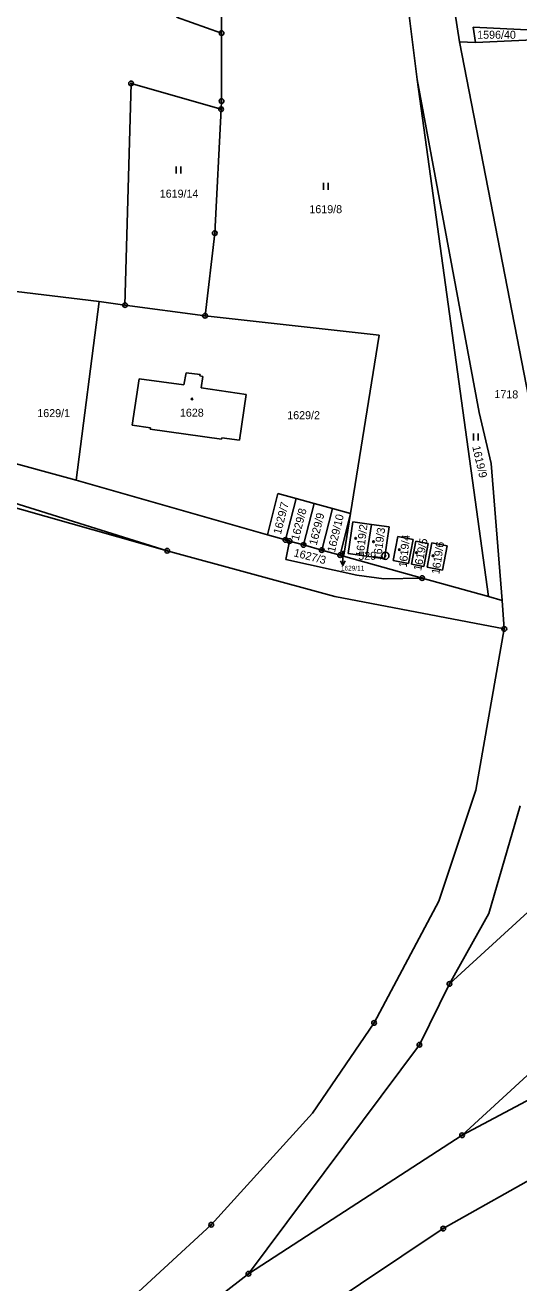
# Model space of a CAD drawing. Extents: x -763296 to -761805, y -1153670 to -1152034.
# Drawn here: x -762587.9 to -762483, y -1153075 to -1152808 of the extents above; entities that cross this region are included whole.
import ezdxf

# ---------------------------------------------------------------- set-up
doc = ezdxf.new("R2010")
doc.units = 0
for name, color, linetype in [('Vrstva 1', 7, 'Continuous'), ('Vrstva 16', 7, 'Continuous'), ('Vrstva 17', 7, 'Continuous'), ('Vrstva 18', 7, 'Continuous'), ('Vrstva 19', 7, 'Continuous'), ('Vrstva 24', 7, 'Continuous'), ('Vrstva 25', 7, 'Continuous'), ('Vrstva 62', 7, 'Continuous')]:
    doc.layers.add(name, color=color, linetype=linetype)

msp = doc.modelspace()

# ---------------------------------------------------------------- linework, layer by layer
at = {"layer": 'Vrstva 1'}
for p, q in [((-762508.36, -1152789.42), (-762504.64, -1152819.5)), ((-762499.2, -1152789.04), (-762495.62, -1152811.48)), ((-762546.17, -1152801.38), (-762546.17, -1152809.66)), ((-762546.17, -1152809.66), (-762555.78, -1152806.25)), ((-762546.17, -1152824.1), (-762546.17, -1152809.66)), ((-762492.69, -1152808.38), (-762492.22, -1152811.65)), ((-762469.39, -1152809.59), (-762492.69, -1152808.38)), ((-762469.13, -1152810.58), (-762492.22, -1152811.65)), ((-762492.22, -1152811.65), (-762495.62, -1152811.48)), ((-762495.62, -1152811.48), (-762480.87, -1152887.2)), ((-762566.69, -1152867.4), (-762565.41, -1152820.33)), ((-762565.41, -1152820.33), (-762546.26, -1152825.83)), ((-762504.64, -1152819.5), (-762491.44, -1152890.19)), ((-762504.64, -1152819.5), (-762489.47, -1152929.3)), ((-762546.26, -1152825.83), (-762546.17, -1152824.1)), ((-762546.26, -1152825.83), (-762547.62, -1152852.12)), ((-762547.62, -1152852.12), (-762549.69, -1152869.67)), ((-762572.19, -1152866.66), (-762622.59, -1152860.62)), ((-762572.19, -1152866.66), (-762577.03, -1152904.55)), ((-762566.69, -1152867.4), (-762572.19, -1152866.66)), ((-762549.69, -1152869.67), (-762566.69, -1152867.4)), ((-762549.69, -1152869.67), (-762512.7, -1152873.81)), ((-762518.78, -1152911.67), (-762512.7, -1152873.81)), ((-762554.17, -1152884.35), (-762553.71, -1152881.78)), ((-762553.71, -1152881.78), (-762550.74, -1152882.15)), ((-762550.74, -1152882.15), (-762550.77, -1152882.42)), ((-762550.77, -1152882.42), (-762550.12, -1152882.58)), ((-762550.12, -1152882.58), (-762550.5, -1152885)), ((-762565.16, -1152892.92), (-762563.68, -1152883.04)), ((-762563.68, -1152883.04), (-762554.17, -1152884.35)), ((-762550.5, -1152885), (-762540.93, -1152886.37)), ((-762540.93, -1152886.37), (-762542.33, -1152896.12)), ((-762491.44, -1152890.19), (-762488.88, -1152901.06)), ((-762561.28, -1152893.46), (-762565.16, -1152892.92)), ((-762561.33, -1152893.76), (-762561.28, -1152893.46)), ((-762546.16, -1152895.89), (-762561.33, -1152893.76)), ((-762546.12, -1152895.59), (-762546.16, -1152895.89)), ((-762542.33, -1152896.12), (-762546.12, -1152895.59)), ((-762577.03, -1152904.55), (-762602.71, -1152897.57)), ((-762616.34, -1152901.22), (-762557.73, -1152919.56)), ((-762488.88, -1152901.06), (-762486.58, -1152930.11)), ((-762612.33, -1152904.1), (-762557.73, -1152919.56)), ((-762536.44, -1152916.16), (-762577.03, -1152904.55)), ((-762536.44, -1152916.16), (-762534.2, -1152907.38)), ((-762534.2, -1152907.38), (-762530.35, -1152908.45)), ((-762530.35, -1152908.45), (-762532.6, -1152917.27)), ((-762530.35, -1152908.45), (-762526.49, -1152909.52)), ((-762526.49, -1152909.52), (-762528.74, -1152918.34)), ((-762526.49, -1152909.52), (-762522.64, -1152910.6)), ((-762522.64, -1152910.6), (-762524.89, -1152919.42)), ((-762522.64, -1152910.6), (-762518.78, -1152911.67)), ((-762518.78, -1152911.67), (-762520.98, -1152920.5)), ((-762520.13, -1152920.06), (-762518.78, -1152911.67)), ((-762518.26, -1152913.43), (-762519.27, -1152920.16)), ((-762518.26, -1152913.43), (-762514.34, -1152913.96)), ((-762514.34, -1152913.96), (-762515.35, -1152920.75)), ((-762514.34, -1152913.96), (-762510.56, -1152914.52)), ((-762510.56, -1152914.52), (-762511.58, -1152921.31)), ((-762532.6, -1152917.27), (-762536.44, -1152916.16)), ((-762531.74, -1152917.51), (-762532.6, -1152917.27)), ((-762532.54, -1152921.39), (-762531.74, -1152917.51)), ((-762531.74, -1152917.51), (-762528.74, -1152918.34)), ((-762509.71, -1152921.67), (-762508.73, -1152916.52)), ((-762508.73, -1152916.52), (-762505.49, -1152917.15)), ((-762505.49, -1152917.15), (-762506.47, -1152922.29)), ((-762505.83, -1152922.41), (-762504.9, -1152917.52)), ((-762504.9, -1152917.52), (-762502.25, -1152918.04)), ((-762557.73, -1152919.56), (-762522.11, -1152929.29)), ((-762528.74, -1152918.34), (-762524.89, -1152919.42)), ((-762524.89, -1152919.42), (-762520.98, -1152920.5)), ((-762520.13, -1152920.06), (-762520.24, -1152920.71)), ((-762519.27, -1152920.16), (-762515.35, -1152920.75)), ((-762502.25, -1152918.04), (-762503.18, -1152922.92)), ((-762502.47, -1152923.06), (-762501.48, -1152917.91)), ((-762501.48, -1152917.91), (-762498.24, -1152918.53)), ((-762498.24, -1152918.53), (-762499.23, -1152923.68)), ((-762517.46, -1152924.74), (-762532.54, -1152921.39)), ((-762520.98, -1152920.5), (-762520.24, -1152920.71)), ((-762520.24, -1152920.71), (-762503.56, -1152925.36)), ((-762515.35, -1152920.75), (-762511.58, -1152921.31)), ((-762506.47, -1152922.29), (-762509.71, -1152921.67)), ((-762503.18, -1152922.92), (-762505.83, -1152922.41)), ((-762511.67, -1152925.56), (-762517.46, -1152924.74)), ((-762503.56, -1152925.36), (-762511.67, -1152925.56)), ((-762503.56, -1152925.36), (-762489.47, -1152929.3)), ((-762499.23, -1152923.68), (-762502.47, -1152923.06)), ((-762486.1, -1152936.16), (-762522.11, -1152929.29)), ((-762489.47, -1152929.3), (-762486.58, -1152930.11)), ((-762486.58, -1152930.11), (-762486.1, -1152936.16)), ((-762486.1, -1152936.16), (-762492.13, -1152970.38)), ((-762492.13, -1152970.38), (-762500.03, -1152993.98)), ((-762482.73, -1152973.76), (-762489.42, -1152996.62)), ((-762461.33, -1152978.19), (-762497.75, -1153011.54)), ((-762500.03, -1152993.98), (-762513.78, -1153019.83)), ((-762489.42, -1152996.62), (-762497.75, -1153011.54)), ((-762446.36, -1152998.85), (-762495.08, -1153043.69)), ((-762504.13, -1153024.45), (-762497.75, -1153011.54)), ((-762513.78, -1153019.83), (-762526.87, -1153038.97)), ((-762540.48, -1153073.09), (-762504.13, -1153024.45)), ((-762468.55, -1153029.57), (-762495.08, -1153043.69)), ((-762526.87, -1153038.97), (-762548.36, -1153062.69)), ((-762495.08, -1153043.69), (-762522.65, -1153061.57)), ((-762468.54, -1153046.27), (-762499.07, -1153063.48)), ((-762522.65, -1153061.57), (-762540.48, -1153073.09)), ((-762548.36, -1153062.69), (-762617.35, -1153126.13)), ((-762499.07, -1153063.48), (-762532.59, -1153085.86)), ((-762540.48, -1153073.09), (-762587.26, -1153109.26))]:
    msp.add_line(p, q, dxfattribs=at)
at = {"layer": 'Vrstva 16'}
for p in [(-762520.4, -1152919.63), (-762520.399, -1152922.69)]:
    msp.add_line(p, (-762520.4, -1152919.69), dxfattribs=at)
msp.add_lwpolyline([(-762519.899, -1152921.69), (-762520.399, -1152922.69), (-762520.899, -1152921.69)], dxfattribs=at)
at = {"layer": 'Vrstva 24'}
for centre, radius in [((-762546.17, -1152809.66), 0.5), ((-762546.17, -1152809.66), 0.1), ((-762565.41, -1152820.33), 0.5), ((-762565.41, -1152820.33), 0.1), ((-762546.17, -1152824.1), 0.5), ((-762546.17, -1152824.1), 0.1), ((-762546.26, -1152825.83), 0.5), ((-762546.26, -1152825.83), 0.1), ((-762547.62, -1152852.12), 0.5), ((-762547.62, -1152852.12), 0.1), ((-762566.69, -1152867.4), 0.5), ((-762566.69, -1152867.4), 0.1), ((-762549.69, -1152869.67), 0.5), ((-762549.69, -1152869.67), 0.1), ((-762532.6, -1152917.27), 0.5), ((-762532.6, -1152917.27), 0.1), ((-762531.74, -1152917.51), 0.5), ((-762531.74, -1152917.51), 0.1), ((-762557.73, -1152919.56), 0.5), ((-762557.73, -1152919.56), 0.1), ((-762528.74, -1152918.34), 0.5), ((-762528.74, -1152918.34), 0.1), ((-762524.89, -1152919.42), 0.5), ((-762524.89, -1152919.42), 0.1), ((-762520.98, -1152920.5), 0.5), ((-762511.36, -1152920.64), 0.75), ((-762520.98, -1152920.5), 0.1), ((-762511.36, -1152920.64), 0.1), ((-762503.56, -1152925.36), 0.5), ((-762503.56, -1152925.36), 0.1), ((-762486.1, -1152936.16), 0.5), ((-762486.1, -1152936.16), 0.1), ((-762497.75, -1153011.54), 0.5), ((-762497.75, -1153011.54), 0.1), ((-762513.78, -1153019.83), 0.5), ((-762513.78, -1153019.83), 0.1), ((-762504.13, -1153024.45), 0.5), ((-762504.13, -1153024.45), 0.1), ((-762495.08, -1153043.69), 0.5), ((-762495.08, -1153043.69), 0.1), ((-762548.36, -1153062.69), 0.5), ((-762548.36, -1153062.69), 0.1), ((-762499.07, -1153063.48), 0.5), ((-762499.07, -1153063.48), 0.1), ((-762540.48, -1153073.09), 0.5), ((-762540.48, -1153073.09), 0.1)]:
    msp.add_circle(centre, radius, dxfattribs=at)
at = {"layer": 'Vrstva 25'}
for p, q in [((-762555.84, -1152839.48), (-762555.84, -1152837.98)), ((-762554.84, -1152839.48), (-762554.84, -1152837.98)), ((-762524.53, -1152842.94), (-762524.53, -1152841.44)), ((-762523.53, -1152842.94), (-762523.53, -1152841.44)), ((-762492.66, -1152896.16), (-762492.66, -1152894.66)), ((-762491.66, -1152896.16), (-762491.66, -1152894.66))]:
    msp.add_line(p, q, dxfattribs=at)
for centre in [(-762552.47, -1152887.34), (-762517.68, -1152916.92), (-762513.88, -1152917.65), (-762508.4, -1152919.32), (-762504.75, -1152919.97), (-762501.23, -1152920.64)]:
    msp.add_circle(centre, 0.175, dxfattribs=at)

# ---------------------------------------------------------------- texts
at = {"layer": 'Vrstva 17'}
msp.add_text('529', height=1.7, dxfattribs=at).set_placement((-762517.127, -1152921.49))
at = {"layer": 'Vrstva 18'}
for s, height, p in [('1596/40', 1.7, (-762491.867, -1152810.85)), ('1619/14', 1.7, (-762559.308, -1152844.59)), ('1619/8', 1.7, (-762527.516, -1152847.89)), ('1629/1', 1.7, (-762585.32, -1152891.19)), ('1629/2', 1.7, (-762532.222, -1152891.63)), ('1629/11', 0.1, (-762520.626, -1152919.63))]:
    msp.add_text(s, height=height, dxfattribs=at).set_placement(p)
for s, rotation, p in [('1718', 358.78617, (-762488.217, -1152887.129)), ('1619/9', 283.09845, (-762492.926, -1152897.463)), ('1629/7', 75.80232, (-762533.584, -1152916.202)), ('1629/8', 75.45854, (-762529.821, -1152917.524)), ('1629/9', 76.14609, (-762525.971, -1152918.526)), ('1629/10', 76.43257, (-762522.109, -1152920.028)), ('1627/3', 345.66544, (-762530.964, -1152920.716))]:
    msp.add_text(s, height=1.7, rotation=rotation, dxfattribs=at).set_placement(p)
at = {"layer": 'Vrstva 19'}
msp.add_text('1628', height=1.7, dxfattribs=at).set_placement((-762555.019, -1152891.1))
for s, rotation, p in [('1619/2', 83.19347, (-762515.995, -1152920.955)), ('1619/3', 82.44863, (-762512.312, -1152921.663)), ('1619/4', 84.2248, (-762506.845, -1152923.169)), ('1619/5', 78.43792, (-762503.776, -1152923.923)), ('1619/6', 81.30271, (-762499.918, -1152924.637))]:
    msp.add_text(s, height=1.7, rotation=rotation, dxfattribs=at).set_placement(p)
at = {"layer": 'Vrstva 62'}
msp.add_text('1629/11', height=1, dxfattribs=at).set_placement((-762520.82, -1152923.76))

doc.saveas('drawing.dxf')
